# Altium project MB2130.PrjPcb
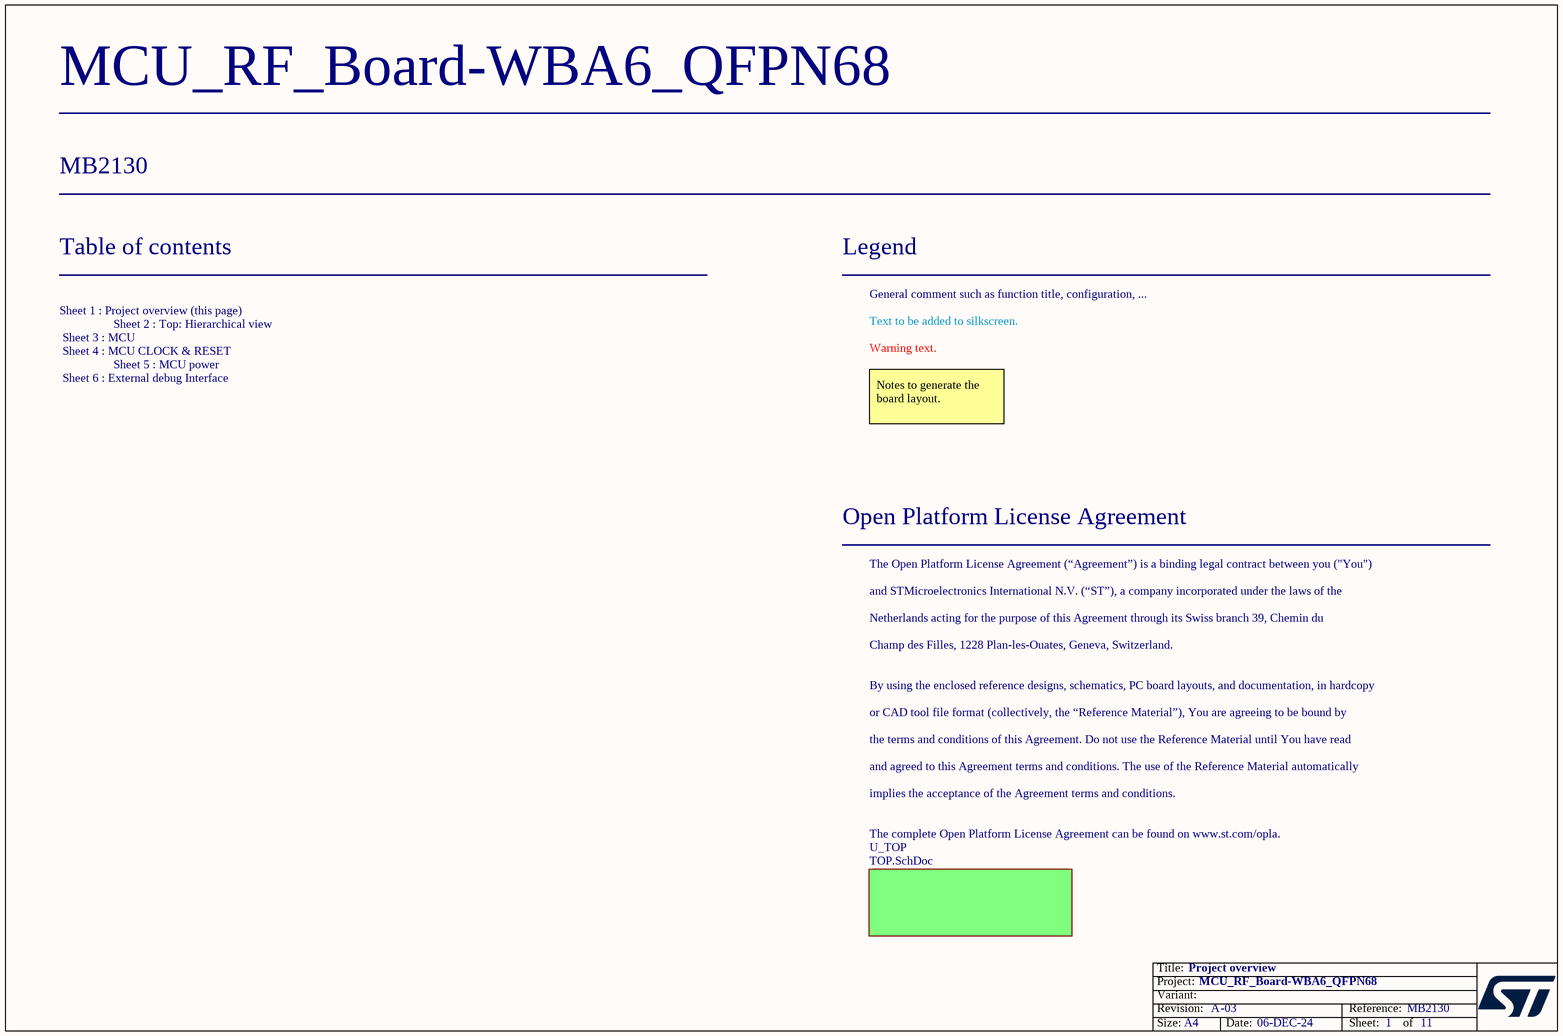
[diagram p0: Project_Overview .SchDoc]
Board_Reference: MB2130; Board_PCB_Revision: A; Board_Name: MCU_RF_Board-WBA6_QFPN68; Board_Document_Date: 06-DEC-24; Board_Assembly_Revision: 03
6 sheets, 86 parts. Net scope: flat (ports and power ports of the same name join across sheets).
Board file: MB2130.PcbDoc
Sheets:
  Project_Overview .SchDoc
    U_TOP = Top.SchDoc
      U_External_Debug_Interface = External_Debug_Interface.SchDoc
      U_MCU = MCU.SchDoc
      U_MCU_Clock&Reset = MCU_Clock&Reset.SchDoc
      U_MCU_Power = MCU_Power.SchDoc

## Sheet Project_Overview .SchDoc: Project overview
size A4; Date: Not used; ApprovedBy: Not used; CheckedBy: Not used; Author: Not used; CompanyName: STMicroelectronics; DrawnBy: Not used; Engineer: Not used; Organization: Not used; Address1: Not used; Address2: Not used; Address3: Not used; Address4: Not used; DocumentNumber: 1; Revision: Not used; SheetNumber: 1; SheetTotal: 11

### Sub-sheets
U_TOP = TOP.SchDoc: no entries

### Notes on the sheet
- Table of contents
- Legend
- General comment such as function title, configuration, ...
- Text to be added to silkscreen.
- Warning text.
- Notes to generate the board layout.
- Open Platform License Agreement
- The Open Platform License Agreement (“Agreement”) is a binding legal contract between you ("You")
- and STMicroelectronics International N.V. (“ST”), a company incorporated under the laws of the
- Netherlands acting for the purpose of this Agreement through its Swiss branch 39, Chemin du
- Champ des Filles, 1228 Plan-les-Ouates, Geneva, Switzerland.
- Sheet 1 : Project overview (this page)
  Sheet 2 : Top: Hierarchical view
  Sheet 3 : MCU
  Sheet 4 : MCU CLOCK & RESET
  Sheet 5 : MCU power
  Sheet 6 : External debug Interface
- By using the enclosed reference designs, schematics, PC board layouts, and documentation, in hardcopy
- or CAD tool file format (collectively, the “Reference Material”), You are agreeing to be bound by
- the terms and conditions of this Agreement. Do not use the Reference Material until You have read
- and agreed to this Agreement terms and conditions. The use of the Reference Material automatically
- implies the acceptance of the Agreement terms and conditions.
- The complete Open Platform License Agreement can be found on www.st.com/opla.

## Sheet Top.SchDoc: Schematic sheet title to update
size A4; Date: Not used; ApprovedBy: Not used; CheckedBy: Not used; Author: Not used; CompanyName: STMicroelectronics; DrawnBy: Not used; Engineer: Not used; Organization: Not used; Address1: Not used; Address2: Not used; Address3: Not used; Address4: Not used; DocumentNumber: Not used; Revision: Not used; SheetNumber: 2; SheetTotal: 11
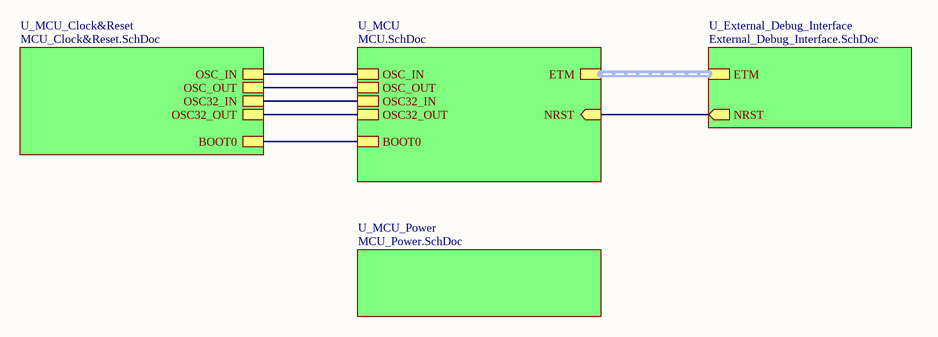
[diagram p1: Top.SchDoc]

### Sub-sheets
U_External_Debug_Interface = External_Debug_Interface.SchDoc: NRST (out), ETM (harness ETM)
U_MCU = MCU.SchDoc: OSC_IN, OSC_OUT, OSC32_IN, OSC32_OUT, ETM (harness ETM), BOOT0, NRST (in)
U_MCU_Clock&Reset = MCU_Clock&Reset.SchDoc: OSC_IN, OSC_OUT, OSC32_IN, OSC32_OUT, BOOT0
U_MCU_Power = MCU_Power.SchDoc: no entries

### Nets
(unnamed): sheet U_External_Debug_Interface/NRST, sheet U_MCU/NRST
(unnamed): sheet U_MCU/OSC_IN, sheet U_MCU_Clock&Reset/OSC_IN  [a separate net that carries the same name]
(unnamed): sheet U_MCU/OSC_OUT, sheet U_MCU_Clock&Reset/OSC_OUT  [a separate net that carries the same name]
(unnamed): sheet U_MCU/OSC32_IN, sheet U_MCU_Clock&Reset/OSC32_IN  [a separate net that carries the same name]
(unnamed): sheet U_MCU/OSC32_OUT, sheet U_MCU_Clock&Reset/OSC32_OUT  [a separate net that carries the same name]
(unnamed): sheet U_MCU/BOOT0, sheet U_MCU_Clock&Reset/BOOT0  [a separate net that carries the same name]

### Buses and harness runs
harness sheet U_External_Debug_Interface/ETM = sheet U_MCU/ETM

## Sheet External_Debug_Interface.SchDoc: External_Debug_Interface
size A4; Date: Not used; ApprovedBy: Not used; CheckedBy: Not used; Author: Not used; CompanyName: STMicroelectronics; DrawnBy: Not used; Engineer: Not used; Organization: Not used; Address1: Not used; Address2: Not used; Address3: Not used; Address4: Not used; DocumentNumber: Not used; Revision: Not used; SheetNumber: 11; SheetTotal: 11
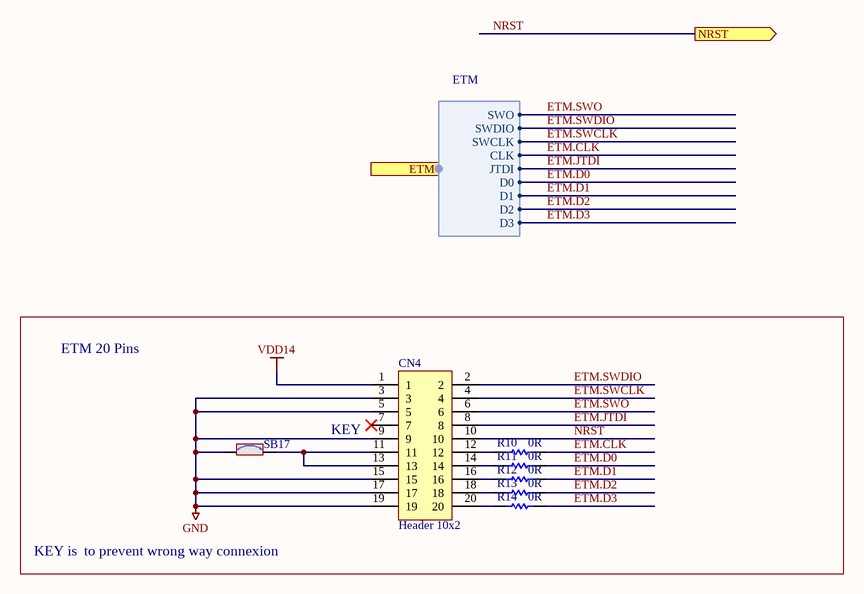
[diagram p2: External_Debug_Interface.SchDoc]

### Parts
CN4  Header 10x2  [CON_SAMTEC_FTSH-110-01-L-DV]
R10  value 0R  [R0402]  (hidden comment: Resistor)
R11  value 0R  [R0402]  (hidden comment: Resistor)
R12  value 0R  [R0402]  (hidden comment: Resistor)
R13  value 0R  [R0402]  (hidden comment: Resistor)
R14  value 0R  [R0402]  (hidden comment: Resistor)
SB17  SB_ON  [SOLDER-BRIDGE_R0402-0R]  (value not drawn)

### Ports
ETM (harness ETM), NRST (out)

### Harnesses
ETM: CLK, D0, D1, D2, JTDI, SWCLK, SWDIO, SWO, D3

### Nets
GND: CN4.3 CN4.5 CN4.9 CN4.15 CN4.17 CN4.19 SB17.1
VDD14: CN4.1
ETM.CLK: R10.2 ; port ETM.CLK
ETM.D0: R11.2 ; port ETM.D0
ETM.D1: R12.2 ; port ETM.D1
ETM.D2: R13.2 ; port ETM.D2
ETM.D3: R14.2 ; port ETM.D3
ETM.JTDI: CN4.8 ; port ETM.JTDI
ETM.SWCLK: CN4.4 ; port ETM.SWCLK
ETM.SWDIO: CN4.2 ; port ETM.SWDIO
ETM.SWO: CN4.6 ; port ETM.SWO
NRST: CN4.10 ; port NRST
NetCN4_11: CN4.11 CN4.13 SB17.2
NetCN4_12: CN4.12 R10.1
NetCN4_14: CN4.14 R11.1
NetCN4_16: CN4.16 R12.1
NetCN4_18: CN4.18 R13.1
NetCN4_20: CN4.20 R14.1

Not connected (* = marked no-connect by the designer): CN4 7*

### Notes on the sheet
- ETM 20 Pins
- KEY
- KEY is  to prevent wrong way connexion

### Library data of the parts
CN4 = MCD-00557: Header, 10x2, 1.27mm, VR, SMD, T=3.05mm; BMS_Part_Number: 9183690; Part_Type: Connector; Part_Preference: Recommended; Manufacturer: SAMTEC; Manufacturer_Part_Number: FTSH-110-01-L-DV; Order_Code_RS: 767-6774; Component_Country_Of_Origin: China, Costa Rica, Malaysia, United States, Vietnam; ShowFields: YES; ID: 3188
R10-R14 = MCD-00052: Resistor, 0R, 0402, +/-5%, 1/16W; Part_Preference: Recommended; Manufacturer: YAGEO; Manufacturer_Part_Number: RC0402JR-070RL; Order_Code_RS: 9232516RL; Component_Country_Of_Origin: China; ShowFields: YES; ID: 2540
SB17 = MCD-01618: Solder Bridge 0402 ON; Part_Type: Misc; Part_Preference: Recommended; Manufacturer: YAGEO; Manufacturer_Part_Number: RC0402JR-070RL; Order_Code_RS: 618-5804; Component_Country_Of_Origin: China

## Sheet MCU.SchDoc: MCU
size A3; Date: Not used; ApprovedBy: Not used; CheckedBy: Not used; Author: Not used; CompanyName: STMicroelectronics; DrawnBy: Not used; Engineer: Not used; Organization: Not used; Address1: Not used; Address2: Not used; Address3: Not used; Address4: Not used; DocumentNumber: Not used; Revision: Not used; SheetNumber: 3; SheetTotal: 11
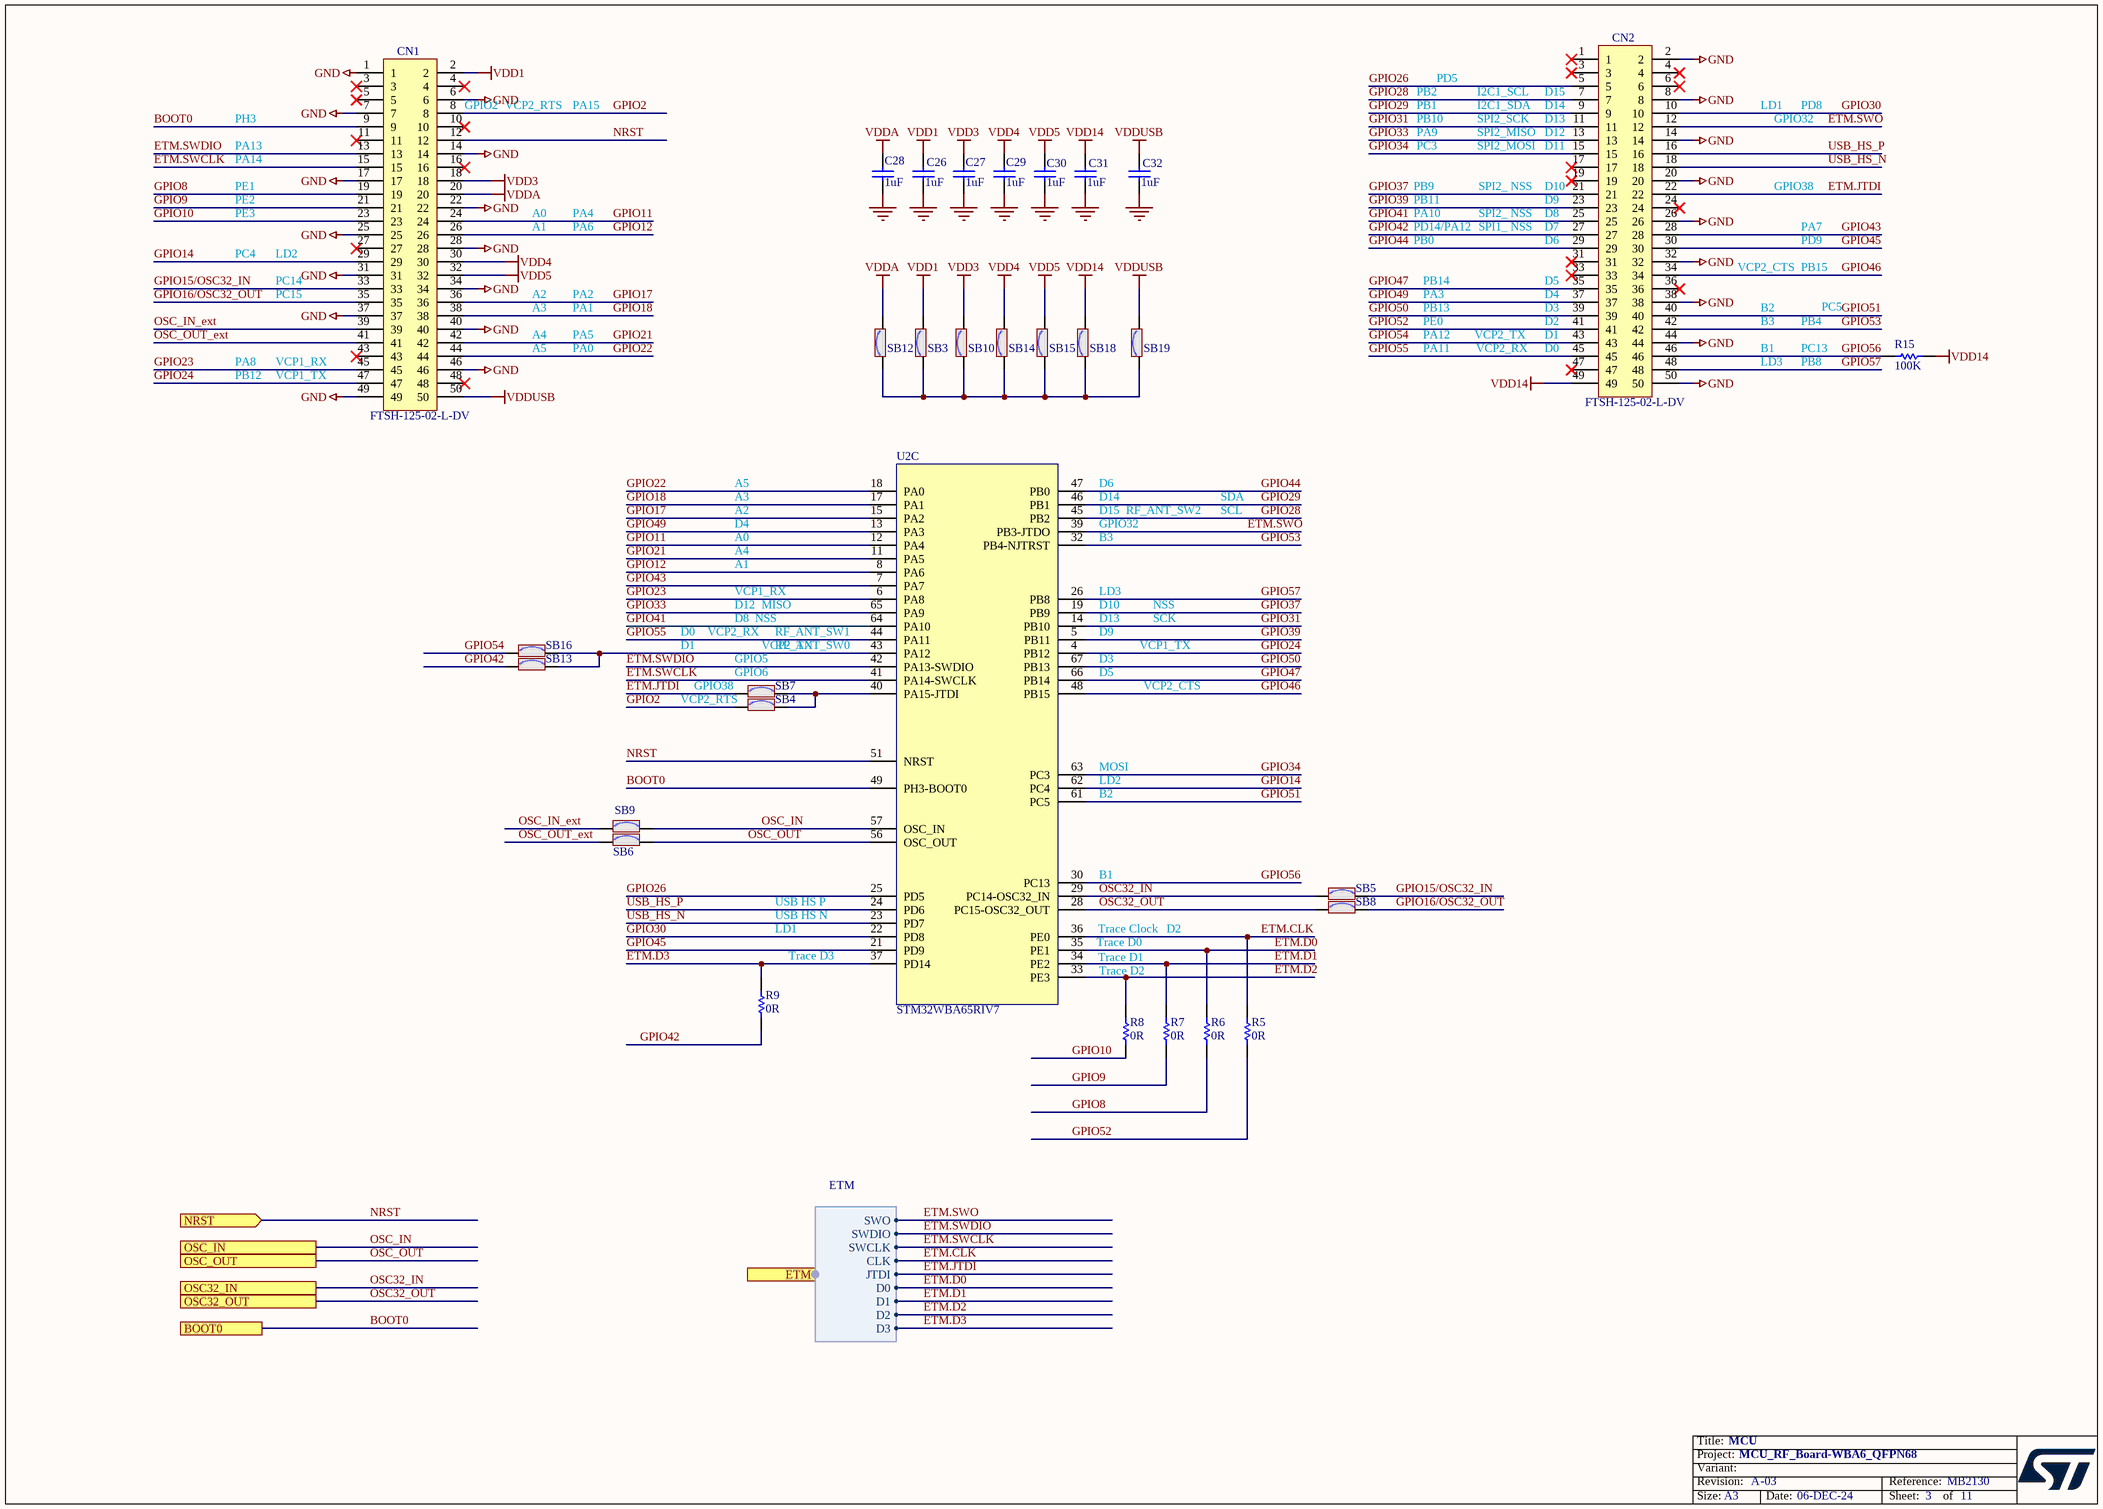
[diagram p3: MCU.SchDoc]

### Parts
C26  value 1uF  [C0402]  (hidden comment: Capacitor)
C27  value 1uF  [C0402]  (hidden comment: Capacitor)
C28  value 1uF  [C0402]  (hidden comment: Capacitor)
C29  value 1uF  [C0402]  (hidden comment: Capacitor)
C30  value 1uF  [C0402]  (hidden comment: Capacitor)
C31  value 1uF  [C0402]  (hidden comment: Capacitor)
C32  value 1uF  [C0402]  (hidden comment: Capacitor)
CN1  FTSH-125-02-L-DV  [CON_SAMTEC_FTSH-125-02-L-DV_INV]
CN2  FTSH-125-02-L-DV  [CON_SAMTEC_FTSH-125-02-L-DV_INV]
R5  value 0R  [R0402]  (hidden comment: Resistor)
R6  value 0R  [R0402]  (hidden comment: Resistor)
R7  value 0R  [R0402]  (hidden comment: Resistor)
R8  value 0R  [R0402]  (hidden comment: Resistor)
R9  value 0R  [R0402]  (hidden comment: Resistor)
R15  value 100K  [R0402]  (hidden comment: Resistor)
SB3  SB_ON  [SOLDER-BRIDGE_R0402-0R]  (value not drawn)
SB4  SB_ON  [SOLDER-BRIDGE_R0402-0R]  (value not drawn)
SB5  SB_ON  [SOLDER-BRIDGE_R0402-0R]  (value not drawn)
SB6  SB_ON  [SOLDER-BRIDGE_R0402-0R]  (value not drawn)
SB7  SB_ON  [SOLDER-BRIDGE_R0402-0R]  (value not drawn)
SB8  SB_ON  [SOLDER-BRIDGE_R0402-0R]  (value not drawn)
SB9  SB_ON  [SOLDER-BRIDGE_R0402-0R]  (value not drawn)
SB10  SB_ON  [SOLDER-BRIDGE_R0402-0R]  (value not drawn)
SB12  SB_ON  [SOLDER-BRIDGE_R0402-0R]  (value not drawn)
SB13  SB_ON  [SOLDER-BRIDGE_R0402-0R]  (value not drawn)
SB14  SB_ON  [SOLDER-BRIDGE_R0402-0R]  (value not drawn)
SB15  SB_ON  [SOLDER-BRIDGE_R0402-0R]  (value not drawn)
SB16  SB_ON  [SOLDER-BRIDGE_R0402-0R]  (value not drawn)
SB18  SB_ON  [SOLDER-BRIDGE_R0402-0R]  (value not drawn)
SB19  SB_ON  [SOLDER-BRIDGE_R0402-0R]  (value not drawn)
U2  value STM32WBA65RIV7  [ICC_VFQFPN68-EPAD_8X8_P040]  (hidden comment: STM32WBA65RI)  (part C of 3)

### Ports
BOOT0, ETM (harness ETM), NRST (in), OSC32_IN, OSC32_OUT, OSC_IN, OSC_OUT

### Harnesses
ETM: CLK, D0, D1, D2, JTDI, SWCLK, SWDIO, SWO, D3

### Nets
GND: C26.1 C27.1 C28.1 C29.1 C30.1 C31.1 C32.1 CN1.1 CN1.6 CN1.7 CN1.14 CN1.17 CN1.22 CN1.25 CN1.28 CN1.31 CN1.34 CN1.37 CN1.40 CN1.46 CN1.49 CN2.2 CN2.8 CN2.14 CN2.20 CN2.26 CN2.32 CN2.38 CN2.44 CN2.50
VDD1: C26.2 CN1.2 SB3.2
VDD3: C27.2 CN1.18 SB10.2
VDD4: C29.2 CN1.30 SB14.2
VDD5: C30.2 CN1.32 SB15.2
VDD14: C31.2 CN2.49 R15.2 SB18.2
VDDA: C28.2 CN1.20 SB12.2
VDDUSB: C32.2 CN1.50 SB19.2
BOOT0: CN1.9 U2.49(PH3-BOOT0) ; port BOOT0
ETM.CLK: R5.2 U2.36(PE0) ; port ETM.CLK
ETM.D0: R6.2 U2.35(PE1) ; port ETM.D0
ETM.D1: R7.2 U2.34(PE2) ; port ETM.D1
ETM.D2: R8.2 U2.33(PE3) ; port ETM.D2
ETM.D3: R9.2 U2.37(PD14) ; port ETM.D3
ETM.JTDI: CN2.22 SB7.1 ; port ETM.JTDI
ETM.SWCLK: CN1.15 U2.41(PA14-SWCLK) ; port ETM.SWCLK
ETM.SWDIO: CN1.13 U2.42(PA13-SWDIO) ; port ETM.SWDIO
ETM.SWO: CN2.12 U2.39(PB3-JTDO) ; port ETM.SWO
GPIO2: CN1.8 SB4.1
GPIO8: CN1.19 R6.1
GPIO9: CN1.21 R7.1
GPIO10: CN1.23 R8.1
GPIO11: CN1.24 U2.12(PA4)
GPIO12: CN1.26 U2.8(PA6)
GPIO14: CN1.29 U2.62(PC4)
GPIO15/OSC32_IN: CN1.33 SB5.2
GPIO16/OSC32_OUT: CN1.35 SB8.2
GPIO17: CN1.36 U2.15(PA2)
GPIO18: CN1.38 U2.17(PA1)
GPIO21: CN1.42 U2.11(PA5)
GPIO22: CN1.44 U2.18(PA0)
GPIO23: CN1.45 U2.6(PA8)
GPIO24: CN1.47 U2.4(PB12)
GPIO26: CN2.5 U2.25(PD5)
GPIO28: CN2.7 U2.45(PB2)
GPIO29: CN2.9 U2.46(PB1)
GPIO30: CN2.10 U2.22(PD8)
GPIO31: CN2.11 U2.14(PB10)
GPIO33: CN2.13 U2.65(PA9)
GPIO34: CN2.15 U2.63(PC3)
GPIO37: CN2.21 U2.19(PB9)
GPIO39: CN2.23 U2.5(PB11)
GPIO41: CN2.25 U2.64(PA10)
GPIO42: CN2.27 R9.1 SB13.1
GPIO43: CN2.28 U2.7(PA7)
GPIO44: CN2.29 U2.47(PB0)
GPIO45: CN2.30 U2.21(PD9)
GPIO46: CN2.34 U2.48(PB15)
GPIO47: CN2.35 U2.66(PB14)
GPIO49: CN2.37 U2.13(PA3)
GPIO50: CN2.39 U2.67(PB13)
GPIO51: CN2.40 U2.61(PC5)
GPIO52: CN2.41 R5.1
GPIO53: CN2.42 U2.32(PB4-NJTRST)
GPIO54: CN2.43 SB16.1
GPIO55: CN2.45 U2.44(PA11)
GPIO56: CN2.46 R15.1 U2.30(PC13)
GPIO57: CN2.48 U2.26(PB8)
NRST: CN1.12 U2.51(NRST) ; port NRST
OSC32_IN: SB5.1 U2.29(PC14-OSC32_IN) ; port OSC32_IN
OSC32_OUT: SB8.1 U2.28(PC15-OSC32_OUT) ; port OSC32_OUT
OSC_IN: SB9.2 U2.57(OSC_IN) ; port OSC_IN
OSC_IN_ext: CN1.39 SB9.1
OSC_OUT: SB6.2 U2.56(OSC_OUT) ; port OSC_OUT
OSC_OUT_ext: CN1.41 SB6.1
USB_HS_N: CN2.18 U2.23(PD7)
USB_HS_P: CN2.16 U2.24(PD6)
NetSB3_1: SB3.1 SB10.1 SB12.1 SB14.1 SB15.1 SB18.1 SB19.1
NetSB4_2: SB4.2 SB7.2 U2.40(PA15-JTDI)
NetSB13_2: SB13.2 SB16.2 U2.43(PA12)

Not connected (* = marked no-connect by the designer): CN1 3* 4* 5* 10* 11* 16* 27* 43* 48*; CN2 1* 3* 4* 6* 17* 19* 24* 31* 33* 36* 47*

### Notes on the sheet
- (near CN1) GPIO2
- VCP2_RTS
- PA15
- PB1
- PB2
- PD5
- I2C1_SCL
- I2C1_SDA
- (near CN2) D14
- (near CN2) D15
- LD1
- PD8
- PH3
- PA13
- PA14
- PA9
- PB10
- PC3
- SPI2_SCK
- SPI2_MOSI
- SPI2_MISO
- (near CN2) D11
- (near CN2) D13
- (near CN2) D12
- GPIO32
- PE1
- PE2
- PE3
- A0
- A1
- PA6
- PA4
- PA10
- PB0
- PB11
- PB9
- PD14/PA12
- SPI2_ NSS
- SPI1_ NSS
- (near CN2) D10
- (near CN2) D9
- (near CN2) D8
- (near CN2) D7
- (near CN2) D6
- GPIO38
- PD9
- PA7
- PC4
- PC14
- PC15
- LD2
- A2
- A3
- PA1
- PA2
- PB14
- PB13
- PA3
- (near CN2) D5
- (near CN2) D4
- (near CN2) D3
- VCP2_CTS
- B2
- PB15
- PC5
- PA8
- PB12
- VCP1_RX
- VCP1_TX
- A4
- A5
- PA0
- PA5
- PA11
- PA12
- PE0
- VCP2_TX
- VCP2_RX
- (near CN2) D1
- (near CN2) D2
- (near CN2) D0
- LD3
- B1
- B3
- PB8
- PB4
- PC13
- (near U2) D15
- (near U2) D14
- (near U2) D6
- RF_ANT_SW2
- SCL
- SDA
- D4
- (near U2) GPIO32
- (near U2) B3
- D0
- D1
- D8  NSS
- D12
- MISO
- RF_ANT_SW1
- RF_ANT_SW0
- (near U2) LD3
- (near U2) D13
- (near U2) D10
- (near U2) D9
- SCK
- NSS
- GPIO5
- (near SB7) GPIO6
- (near U2) D3
- (near U2) D5
- (near U2) LD2
- (near U2) MOSI
- (near U2) B2
- USB HS N
- USB HS P
- (near U2) B1
- Trace D3
- (near U2) Trace D0
- (near U2) Trace Clock
- Trace D1
- Trace D2
- D2

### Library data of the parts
C26-C32 = MCD-01722: Capacitor, MLCC, 1uF, 10V, X5R, +/-10%, 0402, T=0.5mm; Part_Preference: Recommended; Manufacturer: YAGEO; Manufacturer_Part_Number: CC0402KRX5R6BB105; Component_Country_Of_Origin: China
CN1 CN2 = MCD-02746: Header, 25x2, 12.7mm, VR, SMD, T=4.83mm; Part_Type: Connector; Part_Preference: Recommended; Manufacturer: SAMTEC; Value: Header 25x2; ShowFields: YES; ID: 4858; Component_Country_Of_Origin: China, Costa Rica, Malaysia, USA, Vietnam
R5-R9 = MCD-00052: Resistor, 0R, 0402, +/-5%, 1/16W; Part_Preference: Recommended; Manufacturer: YAGEO; Manufacturer_Part_Number: RC0402JR-070RL; Order_Code_RS: 618-5804; Component_Country_Of_Origin: China; ShowFields: YES; ID: 2540
R15 = MCD-00059: Resistor, 100K, 0402, +/-1%, 1/16W; Part_Preference: Recommended; Manufacturer: YAGEO; Manufacturer_Part_Number: RC0402FR-07100KL; Component_Country_Of_Origin: China
SB3-SB10 SB12-SB16 SB18 SB19 = MCD-01618: as SB17 on sheet External_Debug_Interface
U2 = MCD-03837: MCU, ARM Cortex-M33, 2MB Flash, KB SRAM, Crypto, RF 2.4GHz, BLE, 802.15.4; Part_Type: IC; Part_Preference: Recommended; Manufacturer: STMICROELECTRONICS; Component_Country_Of_Origin: Unknown; ShowFields: YES; ID: 5953

## Sheet MCU_Clock&Reset.SchDoc: MCU CLOCK & RESET
size A4; Date: Not used; ApprovedBy: Not used; CheckedBy: Not used; Author: Not used; CompanyName: STMicroelectronics; DrawnBy: Not used; Engineer: Not used; Organization: Not used; Address1: Not used; Address2: Not used; Address3: Not used; Address4: Not used; DocumentNumber: Not used; Revision: Not used; SheetNumber: 4; SheetTotal: 11
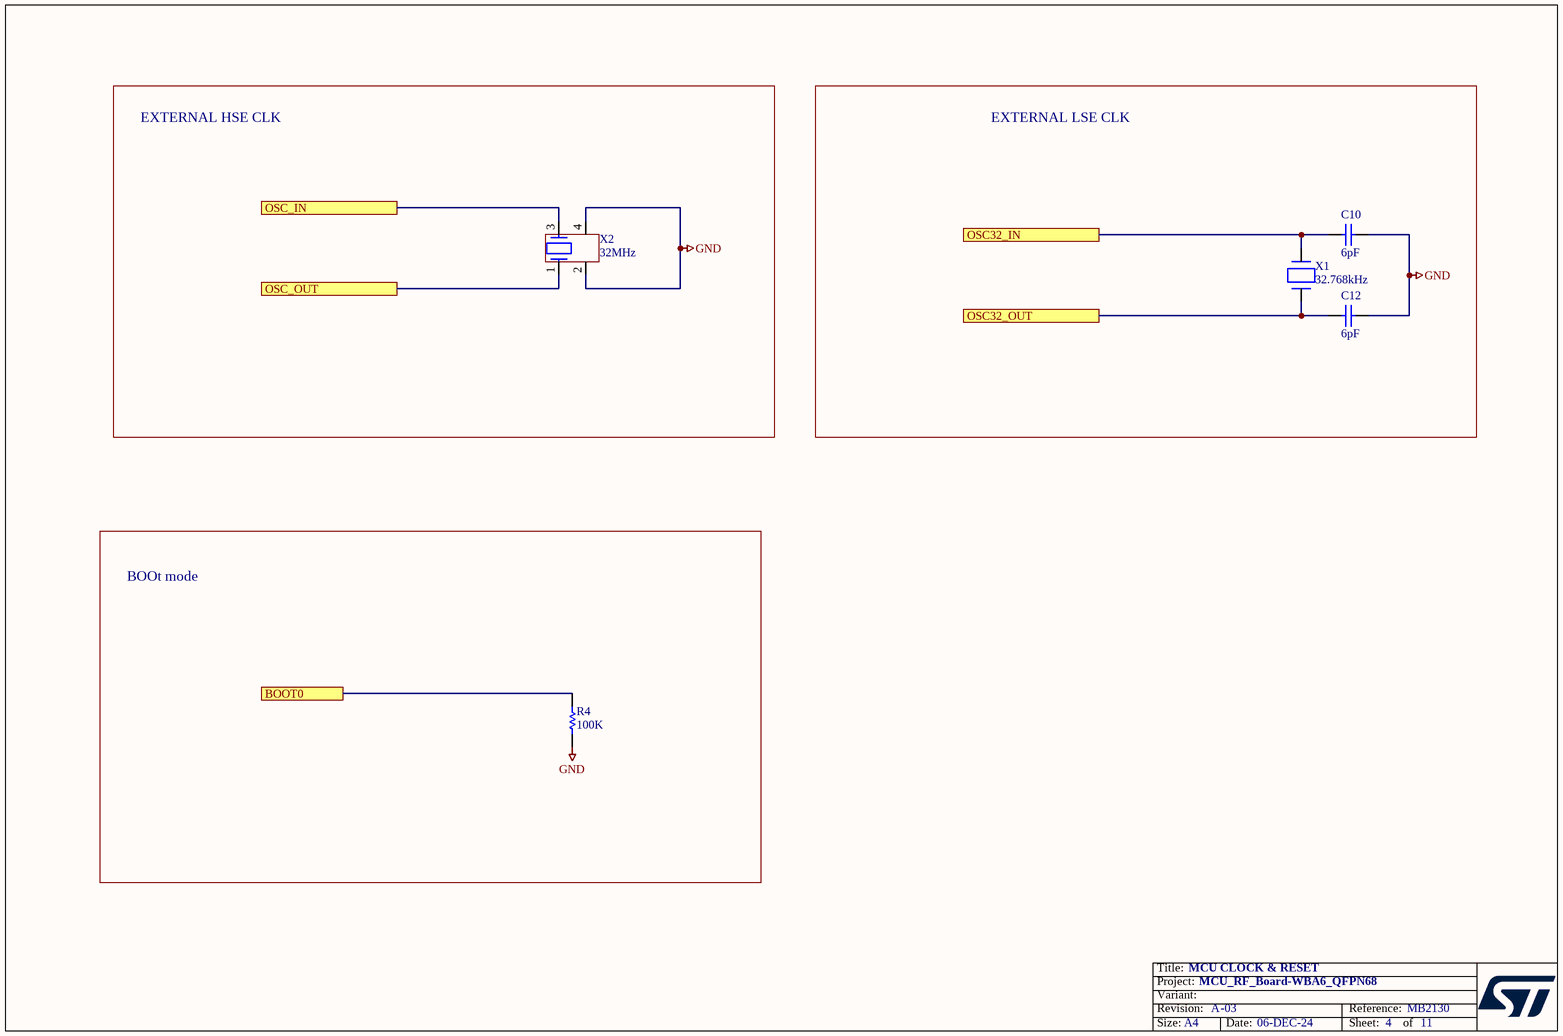
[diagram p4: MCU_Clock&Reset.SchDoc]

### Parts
C10  value 6pF  [C0402]  (hidden comment: Capacitor)
C12  value 6pF  [C0402]  (hidden comment: Capacitor)
R4  value 100K  [R0402]  (hidden comment: Resistor)
X1  value 32.768kHz  [CRY_NX1610SE_2P]  (hidden comment: XTAL_2_PINS)
X2  value 32MHz  [CRY_NX1612SA_4P]  (hidden comment: XTAL_4_PINS)

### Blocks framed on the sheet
EXTERNAL HSE CLK: X2
EXTERNAL LSE CLK: C10 C12 X1
BOOt mode: R4

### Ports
BOOT0, OSC32_IN, OSC32_OUT, OSC_IN, OSC_OUT

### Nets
GND: C10.1 C12.1 R4.2 X2.2 X2.4
BOOT0: R4.1 ; port BOOT0
OSC32_IN: C10.2 X1.1(X1) ; port OSC32_IN
OSC32_OUT: C12.2 X1.2(X2) ; port OSC32_OUT
OSC_IN: X2.3 ; port OSC_IN
OSC_OUT: X2.1 ; port OSC_OUT

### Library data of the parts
C10 C12 = MCD-03185: Capacitor, MLCC, 6pF, 50V, NPO, +/-0,25pF, 0402, T=0.5mm; Part_Preference: Recommended; Manufacturer: MURATA; Manufacturer_Part_Number: GJM1555C1H6R0CB01; Order_Code_RS: 170-6040; Component_Country_Of_Origin: Singapore; ShowFields: YES; ID: 5301
R4 = MCD-00059: as R15 on sheet MCU
X1 = MCD-02579: Crystal, 32.768kHz, 6pF, +/-20ppm, 70KR, 1.6x1mm; Part_Type: Crystal_Osc; Part_Preference: Recommended; Manufacturer: NDK; Manufacturer_Part_Number: NX1610SE-32.768KHZ-EXS00A-MU01501
X2 = MCD-02578: Crystal, 32MHz, 8pF, +/-10ppm, 40R, 1612(metric), T=0.3mm; Part_Type: Crystal_Osc; Part_Preference: Recommended; Manufacturer: NDK; Manufacturer_Part_Number: NX1612SA-32MHZ-EXS00A-CS09166

## Sheet MCU_Power.SchDoc: Board_Power
size A4; Date: Not used; ApprovedBy: Not used; CheckedBy: Not used; Author: Not used; CompanyName: STMicroelectronics; DrawnBy: Not used; Engineer: Not used; Organization: Not used; Address1: Not used; Address2: Not used; Address3: Not used; Address4: Not used; DocumentNumber: Not used; Revision: Not used; SheetNumber: 9; SheetTotal: 11
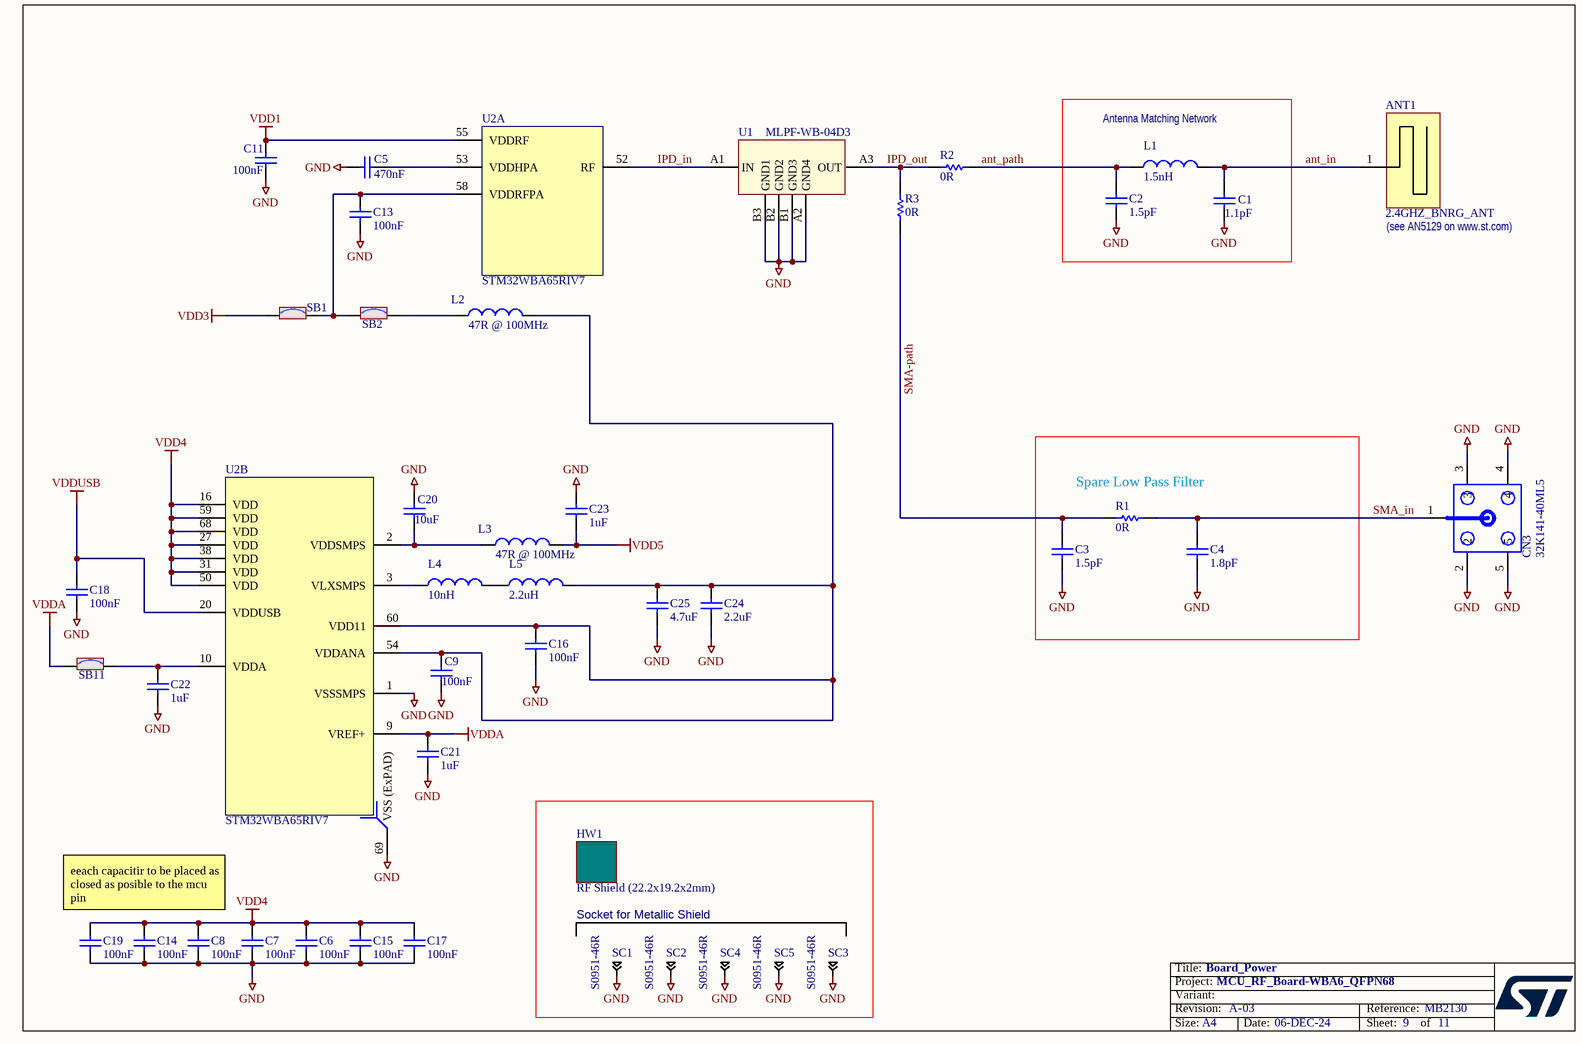
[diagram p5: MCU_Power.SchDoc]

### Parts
ANT1  value 2.4GHZ_BNRG_ANT  [ANT_BT_BNRG_2P4GHZ_MB2032]  (hidden comment: 2.4GHz_BT_ANT)  (no BOM)
C1  value 1.1pF  [C0402]  (hidden comment: Capacitor)
C2  value 1.5pF  [C0402]  (hidden comment: Capacitor)
C3  value 1.5pF  [C0402]  (hidden comment: Capacitor)
C4  value 1.8pF  [C0402]  (hidden comment: Capacitor)
C5  value 470nF  [C0603]  (hidden comment: Capacitor)
C6  value 100nF  [C0402]  (hidden comment: Capacitor)
C7  value 100nF  [C0402]  (hidden comment: Capacitor)
C8  value 100nF  [C0402]  (hidden comment: Capacitor)
C9  value 100nF  [C0402]  (hidden comment: Capacitor)
C11  value 100nF  [C0402]  (hidden comment: Capacitor)
C13  value 100nF  [C0402]  (hidden comment: Capacitor)
C14  value 100nF  [C0402]  (hidden comment: Capacitor)
C15  value 100nF  [C0402]  (hidden comment: Capacitor)
C16  value 100nF  [C0402]  (hidden comment: Capacitor)
C17  value 100nF  [C0402]  (hidden comment: Capacitor)
C18  value 100nF  [C0402]  (hidden comment: Capacitor)
C19  value 100nF  [C0402]  (hidden comment: Capacitor)
C20  value 10uF  [C0603]  (hidden comment: Capacitor)
C21  value 1uF  [C0402]  (hidden comment: Capacitor)
C22  value 1uF  [C0402]  (hidden comment: Capacitor)
C23  value 1uF  [C0402]  (hidden comment: Capacitor)
C24  value 2.2uF  [C0402]  (hidden comment: Capacitor)
C25  value 4.7uF  [C0402]  (hidden comment: Capacitor)
CN3  value 32K141-40ML5  [CON_ROSENBERGER_32K141_40ML5]  (hidden comment: SMA-J-P-H-ST-EM1)
HW1  RF Shield (22.2x19.2x2mm)  [SHIELD_RF_ST-CUSTOM_22P2X19P2_H2]
L1  value 1.5nH  [C0402]  (hidden comment: Inductor)
L2  value 47R @ 100MHz  [IND_0603_H0P8]  (hidden comment: BEAD)
L3  value 47R @ 100MHz  [IND_0603_H0P8]  (hidden comment: BEAD)
L4  value 10nH  [C0402]  (hidden comment: Inductor)
L5  value 2.2uH  [L0805_H0P9]  (hidden comment: Inductor)
R1  value 0R  [R0402]  (hidden comment: Resistor)
R2  value 0R  [R0402]  (hidden comment: Resistor)
R3  value 0R  [R0402]  (hidden comment: Resistor)
SB1  SB_ON  [SOLDER-BRIDGE_R0402-0R]  (value not drawn)
SB2  SB_ON  [SOLDER-BRIDGE_R0402-0R]  (value not drawn)
SB11  SB_ON  [SOLDER-BRIDGE_R0402-0R]  (value not drawn)
SC1  value S0951-46R  [CLIP_HARWIN_S0951-46R]  (hidden comment: Shield-clip_S0951-46R)
SC2  value S0951-46R  [CLIP_HARWIN_S0951-46R]  (hidden comment: Shield-clip_S0951-46R)
SC3  value S0951-46R  [CLIP_HARWIN_S0951-46R]  (hidden comment: Shield-clip_S0951-46R)
SC4  value S0951-46R  [CLIP_HARWIN_S0951-46R]  (hidden comment: Shield-clip_S0951-46R)
SC5  value S0951-46R  [CLIP_HARWIN_S0951-46R]  (hidden comment: Shield-clip_S0951-46R)
U1  MLPF-WB-04D3  [ICC_CSPG_6BUMPS_1X1P60_P050-P0577]
U2  value STM32WBA65RIV7  [ICC_VFQFPN68-EPAD_8X8_P040]  (hidden comment: STM32WBA65RI)  (parts A,B of 3)

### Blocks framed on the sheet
Antenna Matching Network: C1 C2 L1
Spare Low Pass Filter: C3 C4 R1
Socket for Metallic Shield: HW1 SC1-SC5

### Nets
GND: C1.1 C2.2 C3.1 C4.1 C5.1 C6.2 C7.2 C8.2 C9.2 C11.2 C13.2 C14.2 C15.2 C16.1 C17.2 C18.2 C19.2 C20.1 C21.1 C22.1 C23.2 C24.2 C25.1 CN3.2 CN3.3 CN3.4 CN3.5 SC1.1 SC2.1 SC3.1 SC4.1 SC5.1 U1.A2(GND4) U1.B1(GND3) U1.B2(GND2) U1.B3(GND1) U2.1(VSSSMPS) U2.69(VSS_(ExPAD))
VDD1: C11.1 U2.55(VDDRF)
VDD3: SB1.1
VDD4: C6.1 C7.1 C8.1 C14.1 C15.1 C17.1 C19.1 U2.16(VDD) U2.27(VDD) U2.31(VDD) U2.38(VDD) U2.50(VDD) U2.59(VDD) U2.68(VDD)
VDD5: C23.1 L3.2
VDDA: C21.2 SB11.1 U2.9(VREF+)
VDDUSB: C18.1 U2.20(VDDUSB)
ant_in: ANT1.1 C1.2 L1.2
ant_path: C2.1 L1.1 R2.1
IPD_in: U1.A1(IN) U2.52(RF)
IPD_out: R2.2 R3.2 U1.A3(OUT)
SMA-path: C3.2 R1.1 R3.1
SMA_in: C4.2 CN3.1 R1.2
NetC5_2: C5.2 U2.53(VDDHPA)
NetC9_1: C9.1 C16.2 C24.1 C25.2 L2.2 L5.2 U2.54(VDDANA) U2.60(VDD11)
NetC13_1: C13.1 SB1.2 SB2.1 U2.58(VDDRFPA)
NetC20_2: C20.2 L3.1 U2.2(VDDSMPS)
NetC22_2: C22.2 SB11.2 U2.10(VDDA)
NetL2_1: L2.1 SB2.2
NetL4_1: L4.1 U2.3(VLXSMPS)
NetL4_2: L4.2 L5.1

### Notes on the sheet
- (see AN5129 on www.st.com)
- eeach capacitir to be placed as closed as posible to the mcu  pin

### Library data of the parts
ANT1 = MCD-03495: 2.4 GHZ Bluetooth BNRG PCB antenna; Part_Type: Misc; Part_Preference: Recommended; Component_Country_Of_Origin: Unknown; ShowFields: YES; ID: 5611
C1 = MCD-03940: Capacitor, MLCC, 1.1pF, 50V, C0G, +/-0.05pF, 0402, T=0.5mm; Part_Preference: Recommended; Manufacturer: MURATA; Manufacturer_Part_Number: GJM1555C1H1R1WB01; Order_Code_RS: 185-3146; Component_Country_Of_Origin: Japan, Singapore; ShowFields: YES; ID: 6056
C2 = MCD-02994: Capacitor, MLCC, 1.5pF, 50V, C0G, +/-0.25pF, 0402, T=0.5mm; Part_Preference: Recommended; Manufacturer: MURATA; Manufacturer_Part_Number: GRM1555C1H1R5CA01; ShowFields: YES; ID: 5110
C3 = MCD-02994: Capacitor, MLCC, 1.5pF, 50V, C0G, +/-0.25pF, 0402, T=0.5mm; Part_Preference: Recommended; Manufacturer: MURATA; Manufacturer_Part_Number: GRM1555C1H1R5CA01; Component_Country_Of_Origin: Japan°; ShowFields: YES; ID: 5110
C4 = MCD-02995: Capacitor, MLCC, 1.8pF, 50V, C0G, +/-0.25pF, 0402, T=0.5mm; Part_Preference: Recommended; Manufacturer: MURATA; Manufacturer_Part_Number: GRM1555C1H1R8CA01; Order_Code_RS: 723-5357; Component_Country_Of_Origin: Japan°; ShowFields: YES; ID: 5111
C5 = MCD-01006: Capacitor, MLCC, 470nF, 16V, X7R, +/-10%, 0603, T=0.8mm; BMS_Part_Number: 9142003; Part_Preference: Recommended; Manufacturer: YAGEO; Manufacturer_Part_Number: CC0603KRX7R7BB474; Order_Code_RS: 200-6576; Component_Country_Of_Origin: China
C6-C9 C11 C13-C19 = MCD-00006: Capacitor, MLCC, 100nF, 16V, X7R, +/-10%, 0402, T=0.5mm; Manufacturer_Part_Number: CC0402KRX7R7BB104; Manufacturer: YAGEO; Alternate_Manufacturer_Part_Number: GCM155R71C104KA55D; Alternate_Manufacturer: MURATA; Part_Preference: Recommended; Order_Code_RS: 616-9701
C20 = MCD-00243: Capacitor, MLCC, 10uF, 6V3, X5R, +/-10%, 0603, T=0.8mm; Part_Preference: Recommended; Manufacturer: YAGEO; Manufacturer_Part_Number: CC0603KRX5R5BB106
C21 C22 = MCD-01722: as C26 on sheet MCU
C23 = MCD-01722: Capacitor, MLCC, 1uF, 10V, X5R, +/-10%, 0402, T=0.5mm; Part_Preference: Recommended; Manufacturer: YAGEO; Manufacturer_Part_Number: CC0402KRX5R6BB105; Component_Country_Of_Origin: China; ShowFields: YES; ID: 3822
C24 = MCD-01823: Capacitor, MLCC, 2.2uF, 6V3, X5R,+/-10%, 0402, T=0.5mm; Part_Preference: Recommended; Manufacturer: MURATA; Manufacturer_Part_Number: GRM155R60J225KE95D; Order_Code_RS: 172-6478; Component_Country_Of_Origin: Japan; ShowFields: YES; ID: 3923
C25 = MCD-01356: Capacitor, MLCC, 4.7uF, 6V3, X5R, +/-20%, 0402, T=0.5mm; Part_Preference: Recommended; Manufacturer: MURATA; Manufacturer_Part_Number: GRM155R60J475ME47; Order_Code_RS: 814-5230; Component_Country_Of_Origin: Japan; ShowFields: YES; ID: 3456
CN3 = MCD-03951: Straight Jack PCB SMA connector; Part_Preference: Recommended; Manufacturer: ROSENBERGER; Order_Code_RS: NA; ShowFields: YES; ID: 6067
HW1 = MCD-03256: Part_Type: Misc; Part_Preference: Recommended; Manufacturer: TBD; ShowFields: YES; ID: 5372
L1 = MCD-04157: Inductor, 1.5nH, +/-0.3nH, 1A, 100mR, 0402, T=0.5mm; Part_Preference: Recommended; Manufacturer: MURATA; Manufacturer_Part_Number: LQG15HS1N5S02D; Order_Code_RS: 792-6334; ShowFields: YES; ID: 6273
L2 L3 = MCD-04370: Ferrite bead, 47R @100MHz, 500mA, 100mR, 0603, T=0.8mm; Part_Type: Inductor; Part_Preference: Recommended; Manufacturer: WURTH ELEKTRONIK; Manufacturer_Part_Number: 742792608; Order_Code_RS: 669-3986; Component_Country_Of_Origin: Taiwan°; ShowFields: YES; ID: 6486
L4 = MCD-03035: Inductor, 10nH, +/-2%, 0.5A, 260mR, 0402, T=0.5mm; Part_Preference: Recommended; Manufacturer: MURATA; Manufacturer_Part_Number: LQG15HS10NJ02D; Order_Code_RS: 124-8162; Component_Country_Of_Origin: Japan°; ShowFields: YES; ID: 5151
L5 = MCD-01060: Inductor, 2.2uH, +/-20%, 0.7A, 0R156, 0805, T=0.9mm; Part_Preference: Recommended; Manufacturer: MURATA; Manufacturer_Part_Number: LQM21PN2R2MGH; Order_Code_RS: 166-9883; Component_Country_Of_Origin: Japan; ShowFields: YES; ID: 2963
R1-R3 = MCD-00052: as R5 on sheet MCU
SB1 SB2 SB11 = MCD-01618: as SB17 on sheet External_Debug_Interface
SC1-SC5 = MCD-01587: shield clip Harwin S0951-46R to fix RF shielded cavity; Part_Type: Misc; Part_Preference: Recommended; Component_Country_Of_Origin: South Korea
U1 = MCD-03521: IC, 2.4 GHz low pass filter matched to WBA mini board; Part_Preference: Recommended; Manufacturer: STMICROELECTRONICS; Component_Country_Of_Origin: China; ShowFields: YES; ID: 5637
U2 = MCD-03837: as U2 on sheet MCU

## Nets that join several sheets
GND: External_Debug_Interface (7 pins), MCU (30 pins), MCU_Clock&Reset (5 pins), MCU_Power (38 pins)
VDD1: MCU (C26.2 CN1.2 SB3.2), MCU_Power (C11.1 U2.55)
VDD3: MCU (C27.2 CN1.18 SB10.2), MCU_Power (SB1.1)
VDD4: MCU (C29.2 CN1.30 SB14.2), MCU_Power (14 pins)
VDD5: MCU (C30.2 CN1.32 SB15.2), MCU_Power (C23.1 L3.2)
VDD14: External_Debug_Interface (CN4.1), MCU (C31.2 CN2.49 R15.2 SB18.2)
VDDA: MCU (C28.2 CN1.20 SB12.2), MCU_Power (C21.2 SB11.1 U2.9)
VDDUSB: MCU (C32.2 CN1.50 SB19.2), MCU_Power (C18.1 U2.20)
BOOT0: MCU (CN1.9 U2.49), MCU_Clock&Reset (R4.1)
ETM.CLK: External_Debug_Interface (R10.2), MCU (R5.2 U2.36)
ETM.D0: External_Debug_Interface (R11.2), MCU (R6.2 U2.35)
ETM.D1: External_Debug_Interface (R12.2), MCU (R7.2 U2.34)
ETM.D2: External_Debug_Interface (R13.2), MCU (R8.2 U2.33)
ETM.D3: External_Debug_Interface (R14.2), MCU (R9.2 U2.37)
ETM.JTDI: External_Debug_Interface (CN4.8), MCU (CN2.22 SB7.1)
ETM.SWCLK: External_Debug_Interface (CN4.4), MCU (CN1.15 U2.41)
ETM.SWDIO: External_Debug_Interface (CN4.2), MCU (CN1.13 U2.42)
ETM.SWO: External_Debug_Interface (CN4.6), MCU (CN2.12 U2.39)
NRST: External_Debug_Interface (CN4.10), MCU (CN1.12 U2.51)
OSC32_IN: MCU (SB5.1 U2.29), MCU_Clock&Reset (C10.2 X1.1)
OSC32_OUT: MCU (SB8.1 U2.28), MCU_Clock&Reset (C12.2 X1.2)
OSC_IN: MCU (SB9.2 U2.57), MCU_Clock&Reset (X2.3)
OSC_OUT: MCU (SB6.2 U2.56), MCU_Clock&Reset (X2.1)

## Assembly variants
WBA65RI: not fitted C2 C3 C4 C24 C26 C27 C28 C29 C30 C31 C32 CN3 CN4 R3 R15 SB1 SB3 SB4 SB5 SB6 SB8 SB9 SB10 SB12 SB13 SB14 SB15 SB17 SB18 SB19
